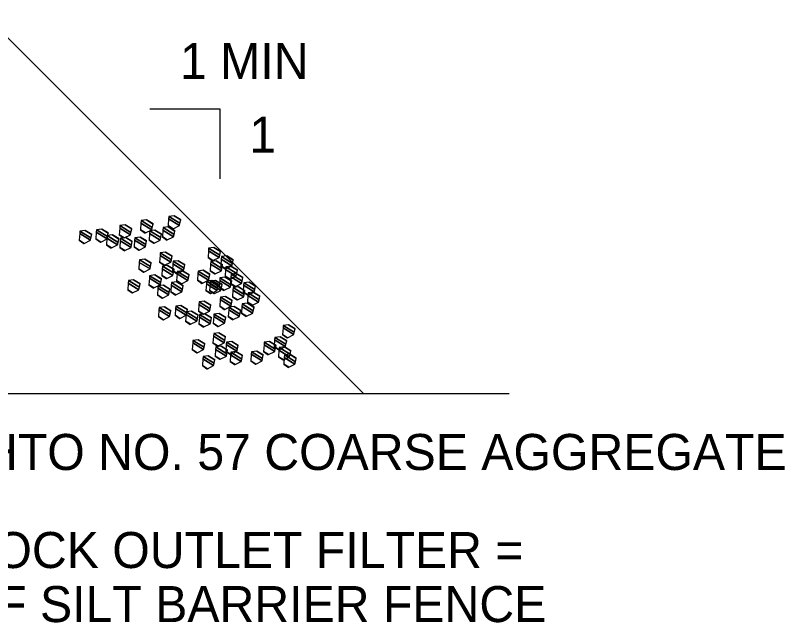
# Model space of a CAD drawing. Extents: x 636462 to 639049, y 299944 to 300538.
# Drawn here: x 637812.7 to 637876.6, y 300272.7 to 300323.2 of the extents above; entities that cross this region are included whole.
import ezdxf

# ---------------------------------------------------------------- set-up
doc = ezdxf.new("R2010")
doc.units = 0
doc.layers.add('Default', color=7, linetype='Continuous')

msp = doc.modelspace()

# ---------------------------------------------------------------- linework, layer by layer
at = {"layer": 'Default'}
for p, q in [((637841.599, 300291.751), (637810.14, 300323.205)), ((637685.207, 300291.751), (637853.724, 300291.751))]:
    msp.add_line(p, q, dxfattribs=at)
msp.add_lwpolyline([(637823.824, 300315.439), (637829.661, 300315.439), (637829.661, 300309.602)], dxfattribs=at)
for points in [[(637823.101, 300305.916), (637823.996, 300305.361), (637824.038, 300305.558), (637823.116, 300306.129)], [(637823.116, 300306.129), (637824.038, 300305.558), (637824.101, 300305.848), (637823.555, 300306.186)], [(637823.555, 300306.186), (637824.101, 300305.848), (637824.103, 300305.858), (637824.103, 300305.858)], [(637825.365, 300305.713), (637825.779, 300305.456), (637826.295, 300305.713), (637825.401, 300306.267)], [(637825.401, 300306.267), (637826.295, 300305.713), (637826.339, 300305.909), (637825.415, 300306.481)], [(637825.415, 300306.481), (637826.339, 300305.909), (637826.403, 300306.196), (637825.852, 300306.538)], [(637825.852, 300306.538), (637826.403, 300306.196), (637826.406, 300306.21), (637826.406, 300306.21)], [(637821.292, 300304.962), (637821.71, 300304.703), (637822.224, 300304.962), (637821.33, 300305.517)], [(637821.33, 300305.517), (637822.224, 300304.962), (637822.267, 300305.157), (637821.344, 300305.729)], [(637821.344, 300305.729), (637822.267, 300305.157), (637822.331, 300305.447), (637821.785, 300305.785)], [(637821.785, 300305.785), (637822.331, 300305.447), (637822.333, 300305.458), (637822.333, 300305.458)], [(637823.061, 300305.361), (637823.476, 300305.104), (637823.996, 300305.361), (637823.101, 300305.916)], [(637824.916, 300305.332), (637825.804, 300304.782), (637825.85, 300304.984), (637824.932, 300305.553)], [(637824.932, 300305.553), (637825.85, 300304.984), (637825.916, 300305.267), (637825.367, 300305.607)], [(637825.745, 300305.44), (637825.745, 300305.44), (637825.779, 300305.456), (637825.365, 300305.713)], [(637825.367, 300305.607), (637825.916, 300305.267), (637825.919, 300305.28), (637825.919, 300305.28)], [(637817.965, 300304.497), (637818.382, 300304.239), (637818.895, 300304.497), (637818.005, 300305.049)], [(637818.005, 300305.049), (637818.895, 300304.497), (637818.939, 300304.694), (637818.021, 300305.264)], [(637818.021, 300305.264), (637818.939, 300304.694), (637819.004, 300304.98), (637818.458, 300305.318)], [(637818.458, 300305.318), (637819.004, 300304.98), (637819.006, 300304.991), (637819.006, 300304.991)], [(637819.344, 300304.608), (637819.76, 300304.35), (637820.278, 300304.608), (637819.382, 300305.164)], [(637819.382, 300305.164), (637820.278, 300304.608), (637820.321, 300304.804), (637819.397, 300305.377)], [(637819.397, 300305.377), (637820.321, 300304.804), (637820.384, 300305.096), (637819.839, 300305.434)], [(637819.839, 300305.434), (637820.384, 300305.096), (637820.386, 300305.104), (637820.386, 300305.104)], [(637820.273, 300304.674), (637821.158, 300304.125), (637821.204, 300304.32), (637820.288, 300304.887)], [(637820.288, 300304.887), (637821.204, 300304.32), (637821.27, 300304.602), (637820.721, 300304.942)], [(637820.721, 300304.942), (637821.27, 300304.602), (637821.273, 300304.614), (637821.273, 300304.614)], [(637821.678, 300304.687), (637821.678, 300304.687), (637821.71, 300304.703), (637821.292, 300304.962)], [(637823.444, 300305.088), (637823.444, 300305.088), (637823.476, 300305.104), (637823.061, 300305.361)], [(637823.771, 300304.517), (637824.185, 300304.261), (637824.7, 300304.517), (637823.81, 300305.069)], [(637823.81, 300305.069), (637824.7, 300304.517), (637824.744, 300304.718), (637823.826, 300305.288)], [(637823.826, 300305.288), (637824.744, 300304.718), (637824.808, 300305.004), (637824.263, 300305.343)], [(637824.263, 300305.343), (637824.808, 300305.004), (637824.811, 300305.015), (637824.811, 300305.015)], [(637824.877, 300304.782), (637825.29, 300304.526), (637825.804, 300304.782), (637824.916, 300305.332)], [(637818.349, 300304.222), (637818.349, 300304.222), (637818.382, 300304.239), (637817.965, 300304.497)], [(637819.73, 300304.335), (637819.73, 300304.335), (637819.76, 300304.35), (637819.344, 300304.608)], [(637820.232, 300304.125), (637820.652, 300303.864), (637821.158, 300304.125), (637820.273, 300304.674)], [(637821.336, 300303.903), (637821.752, 300303.645), (637822.27, 300303.903), (637821.377, 300304.457)], [(637821.377, 300304.457), (637822.27, 300303.903), (637822.313, 300304.1), (637821.393, 300304.671)], [(637821.393, 300304.671), (637822.313, 300304.1), (637822.375, 300304.386), (637821.834, 300304.722)], [(637821.834, 300304.722), (637822.375, 300304.386), (637822.378, 300304.396), (637822.378, 300304.396)], [(637822.529, 300303.947), (637822.946, 300303.688), (637823.462, 300303.947), (637822.57, 300304.5)], [(637822.57, 300304.5), (637823.462, 300303.947), (637823.505, 300304.142), (637822.586, 300304.712)], [(637822.586, 300304.712), (637823.505, 300304.142), (637823.569, 300304.431), (637823.025, 300304.768)], [(637823.025, 300304.768), (637823.569, 300304.431), (637823.571, 300304.44), (637823.571, 300304.44)], [(637824.155, 300304.246), (637824.155, 300304.246), (637824.185, 300304.261), (637823.771, 300304.517)], [(637825.26, 300304.511), (637825.26, 300304.511), (637825.29, 300304.526), (637824.877, 300304.782)], [(637820.616, 300303.846), (637820.616, 300303.846), (637820.652, 300303.864), (637820.232, 300304.125)], [(637821.72, 300303.629), (637821.72, 300303.629), (637821.752, 300303.645), (637821.336, 300303.903)], [(637822.914, 300303.672), (637822.914, 300303.672), (637822.946, 300303.688), (637822.529, 300303.947)], [(637828.674, 300303.071), (637829.088, 300302.814), (637829.608, 300303.071), (637828.713, 300303.626)], [(637828.713, 300303.626), (637829.608, 300303.071), (637829.65, 300303.267), (637828.728, 300303.838)], [(637828.728, 300303.838), (637829.65, 300303.267), (637829.711, 300303.557), (637829.167, 300303.894)], [(637829.167, 300303.894), (637829.711, 300303.557), (637829.713, 300303.567), (637829.713, 300303.567)], [(637822.976, 300302.877), (637823.894, 300302.308), (637823.959, 300302.595), (637823.413, 300302.934)], [(637823.413, 300302.934), (637823.959, 300302.595), (637823.961, 300302.606), (637823.961, 300302.606)], [(637824.647, 300302.685), (637825.059, 300302.43), (637825.581, 300302.685), (637824.685, 300303.241)], [(637824.685, 300303.241), (637825.581, 300302.685), (637825.624, 300302.882), (637824.7, 300303.456)], [(637824.7, 300303.456), (637825.624, 300302.882), (637825.687, 300303.173), (637825.142, 300303.51)], [(637825.142, 300303.51), (637825.687, 300303.173), (637825.688, 300303.18), (637825.688, 300303.18)], [(637829.056, 300302.798), (637829.056, 300302.798), (637829.088, 300302.814), (637828.674, 300303.071)], [(637829.738, 300302.365), (637830.151, 300302.109), (637830.666, 300302.365), (637829.775, 300302.918)], [(637829.775, 300302.918), (637830.666, 300302.365), (637830.711, 300302.563), (637829.79, 300303.134)], [(637829.79, 300303.134), (637830.711, 300302.563), (637830.777, 300302.85), (637830.227, 300303.191)], [(637830.227, 300303.191), (637830.777, 300302.85), (637830.779, 300302.861), (637830.779, 300302.861)], [(637822.922, 300302.111), (637823.339, 300301.852), (637823.85, 300302.111), (637822.961, 300302.662)], [(637822.961, 300302.662), (637823.85, 300302.111), (637823.894, 300302.308), (637822.976, 300302.877)], [(637825.027, 300302.414), (637825.027, 300302.414), (637825.059, 300302.43), (637824.647, 300302.685)], [(637824.862, 300302.134), (637825.757, 300301.579), (637825.8, 300301.777), (637824.877, 300302.349)], [(637824.877, 300302.349), (637825.8, 300301.777), (637825.862, 300302.065), (637825.316, 300302.404)], [(637825.316, 300302.404), (637825.862, 300302.065), (637825.864, 300302.076), (637825.864, 300302.076)], [(637825.709, 300301.979), (637826.122, 300301.723), (637826.639, 300301.979), (637825.749, 300302.531)], [(637825.749, 300302.531), (637826.639, 300301.979), (637826.684, 300302.18), (637825.765, 300302.75)], [(637825.765, 300302.75), (637826.684, 300302.18), (637826.747, 300302.461), (637826.2, 300302.8)], [(637826.2, 300302.8), (637826.747, 300302.461), (637826.75, 300302.475), (637826.75, 300302.475)], [(637828.848, 300301.967), (637829.264, 300301.709), (637829.786, 300301.967), (637828.889, 300302.523)], [(637828.889, 300302.523), (637829.786, 300301.967), (637829.827, 300302.162), (637828.904, 300302.734)], [(637828.904, 300302.734), (637829.827, 300302.162), (637829.888, 300302.454), (637829.345, 300302.79)], [(637829.345, 300302.79), (637829.888, 300302.454), (637829.889, 300302.46), (637829.889, 300302.46)], [(637830.122, 300302.094), (637830.122, 300302.094), (637830.151, 300302.109), (637829.738, 300302.365)], [(637830.13, 300302.076), (637831.02, 300301.524), (637831.064, 300301.723), (637830.146, 300302.293)], [(637830.146, 300302.293), (637831.064, 300301.723), (637831.129, 300302.011), (637830.583, 300302.349)], [(637830.583, 300302.349), (637831.129, 300302.011), (637831.131, 300302.022), (637831.131, 300302.022)], [(637823.306, 300301.836), (637823.306, 300301.836), (637823.339, 300301.852), (637822.922, 300302.111)], [(637824.823, 300301.579), (637825.237, 300301.322), (637825.757, 300301.579), (637824.862, 300302.134)], [(637826.093, 300301.708), (637826.093, 300301.708), (637826.122, 300301.723), (637825.709, 300301.979)], [(637826.061, 300301.14), (637826.474, 300300.883), (637826.995, 300301.14), (637826.101, 300301.694)], [(637826.101, 300301.694), (637826.995, 300301.14), (637827.038, 300301.337), (637826.117, 300301.908)], [(637826.117, 300301.908), (637827.038, 300301.337), (637827.102, 300301.626), (637826.558, 300301.963)], [(637826.558, 300301.963), (637827.102, 300301.626), (637827.102, 300301.629), (637827.102, 300301.629)], [(637827.792, 300301.172), (637828.205, 300300.916), (637828.722, 300301.172), (637827.83, 300301.725)], [(637827.83, 300301.725), (637828.722, 300301.172), (637828.766, 300301.369), (637827.844, 300301.941)], [(637827.844, 300301.941), (637828.766, 300301.369), (637828.83, 300301.656), (637828.279, 300301.997)], [(637828.279, 300301.997), (637828.83, 300301.656), (637828.833, 300301.67), (637828.833, 300301.67)], [(637829.234, 300301.694), (637829.234, 300301.694), (637829.264, 300301.709), (637828.848, 300301.967)], [(637830.089, 300301.524), (637830.505, 300301.267), (637831.02, 300301.524), (637830.13, 300302.076)], [(637830.571, 300301.461), (637831.465, 300300.907), (637831.507, 300301.105), (637830.587, 300301.676)], [(637830.587, 300301.676), (637831.507, 300301.105), (637831.569, 300301.397), (637831.028, 300301.732)], [(637831.028, 300301.732), (637831.569, 300301.397), (637831.57, 300301.403), (637831.57, 300301.403)], [(637822.034, 300300.938), (637822.922, 300300.387), (637822.967, 300300.585), (637822.05, 300301.154)], [(637822.05, 300301.154), (637822.967, 300300.585), (637823.033, 300300.873), (637822.485, 300301.213)], [(637822.485, 300301.213), (637823.033, 300300.873), (637823.035, 300300.883), (637823.035, 300300.883)], [(637823.763, 300300.788), (637824.18, 300300.529), (637824.693, 300300.788), (637823.804, 300301.339)], [(637823.804, 300301.339), (637824.693, 300300.788), (637824.737, 300300.981), (637823.82, 300301.55)], [(637823.82, 300301.55), (637824.737, 300300.981), (637824.803, 300301.272), (637824.257, 300301.611)], [(637824.257, 300301.611), (637824.803, 300301.272), (637824.805, 300301.277), (637824.805, 300301.277)], [(637825.207, 300301.308), (637825.207, 300301.308), (637825.237, 300301.322), (637824.823, 300301.579)], [(637825.63, 300300.98), (637826.552, 300300.408), (637826.615, 300300.696), (637826.069, 300301.035)], [(637826.445, 300300.869), (637826.445, 300300.869), (637826.474, 300300.883), (637826.061, 300301.14)], [(637826.069, 300301.035), (637826.615, 300300.696), (637826.617, 300300.707), (637826.617, 300300.707)], [(637828.17, 300300.899), (637828.17, 300300.899), (637828.205, 300300.916), (637827.792, 300301.172)], [(637828.537, 300300.885), (637829.43, 300300.331), (637829.473, 300300.529), (637828.552, 300301.099)], [(637828.552, 300301.099), (637829.473, 300300.529), (637829.535, 300300.818), (637828.993, 300301.154)], [(637828.846, 300300.884), (637829.738, 300300.331), (637829.782, 300300.527), (637828.86, 300301.099)], [(637828.86, 300301.099), (637829.782, 300300.527), (637829.848, 300300.812), (637829.297, 300301.154)], [(637828.993, 300301.154), (637829.535, 300300.818), (637829.537, 300300.826), (637829.537, 300300.826)], [(637829.297, 300301.154), (637829.848, 300300.812), (637829.851, 300300.826), (637829.851, 300300.826)], [(637829.602, 300300.602), (637830.023, 300300.341), (637830.536, 300300.602), (637829.643, 300301.156)], [(637829.643, 300301.156), (637830.536, 300300.602), (637830.578, 300300.792), (637829.659, 300301.362)], [(637829.659, 300301.362), (637830.578, 300300.792), (637830.641, 300301.082), (637830.098, 300301.419)], [(637830.474, 300301.251), (637830.474, 300301.251), (637830.505, 300301.267), (637830.089, 300301.524)], [(637830.098, 300301.419), (637830.641, 300301.082), (637830.644, 300301.091), (637830.644, 300301.091)], [(637830.53, 300300.907), (637830.946, 300300.65), (637831.465, 300300.907), (637830.571, 300301.461)], [(637831.647, 300300.97), (637832.569, 300300.398), (637832.633, 300300.679), (637832.086, 300301.018)], [(637832.086, 300301.018), (637832.633, 300300.679), (637832.636, 300300.691), (637832.636, 300300.691)], [(637821.993, 300300.387), (637822.407, 300300.131), (637822.922, 300300.387), (637822.034, 300300.938)], [(637822.378, 300300.116), (637822.378, 300300.116), (637822.407, 300300.131), (637821.993, 300300.387)], [(637824.147, 300300.513), (637824.147, 300300.513), (637824.18, 300300.529), (637823.763, 300300.788)], [(637824.467, 300299.947), (637824.883, 300299.688), (637825.403, 300299.947), (637824.508, 300300.502)], [(637824.508, 300300.502), (637825.403, 300299.947), (637825.445, 300300.144), (637824.524, 300300.715)], [(637824.524, 300300.715), (637825.445, 300300.144), (637825.506, 300300.43), (637824.964, 300300.766)], [(637824.964, 300300.766), (637825.506, 300300.43), (637825.508, 300300.44), (637825.508, 300300.44)], [(637825.573, 300300.209), (637825.987, 300299.953), (637826.51, 300300.209), (637825.614, 300300.765)], [(637825.614, 300300.765), (637826.51, 300300.209), (637826.552, 300300.408), (637825.63, 300300.98)], [(637828.496, 300300.331), (637828.912, 300300.073), (637829.43, 300300.331), (637828.537, 300300.885)], [(637828.809, 300300.331), (637829.224, 300300.074), (637829.738, 300300.331), (637828.846, 300300.884)], [(637829.986, 300300.323), (637829.986, 300300.323), (637830.023, 300300.341), (637829.602, 300300.602)], [(637830.915, 300300.634), (637830.915, 300300.634), (637830.946, 300300.65), (637830.53, 300300.907)], [(637830.706, 300299.803), (637831.122, 300299.545), (637831.643, 300299.803), (637830.747, 300300.358)], [(637830.747, 300300.358), (637831.643, 300299.803), (637831.685, 300300), (637830.763, 300300.571)], [(637830.763, 300300.571), (637831.685, 300300), (637831.747, 300300.291), (637831.204, 300300.628)], [(637831.204, 300300.628), (637831.747, 300300.291), (637831.748, 300300.294), (637831.748, 300300.294)], [(637831.594, 300300.203), (637832.014, 300299.943), (637832.524, 300300.203), (637831.632, 300300.757)], [(637831.632, 300300.757), (637832.524, 300300.203), (637832.569, 300300.398), (637831.647, 300300.97)], [(637824.853, 300299.673), (637824.853, 300299.673), (637824.883, 300299.688), (637824.467, 300299.947)], [(637825.957, 300299.938), (637825.957, 300299.938), (637825.987, 300299.953), (637825.573, 300300.209)], [(637828.882, 300300.058), (637828.882, 300300.058), (637828.912, 300300.073), (637828.496, 300300.331)], [(637829.191, 300300.058), (637829.191, 300300.058), (637829.224, 300300.074), (637828.809, 300300.331)], [(637829.687, 300299.561), (637830.579, 300299.008), (637830.623, 300299.201), (637829.701, 300299.773)], [(637829.701, 300299.773), (637830.623, 300299.201), (637830.688, 300299.486), (637830.138, 300299.827)], [(637830.138, 300299.827), (637830.688, 300299.486), (637830.69, 300299.498), (637830.69, 300299.498)], [(637831.091, 300299.53), (637831.091, 300299.53), (637831.122, 300299.545), (637830.706, 300299.803)], [(637831.98, 300299.926), (637831.98, 300299.926), (637832.014, 300299.943), (637831.594, 300300.203)], [(637831.946, 300299.36), (637832.361, 300299.103), (637832.876, 300299.36), (637831.988, 300299.911)], [(637831.988, 300299.911), (637832.876, 300299.36), (637832.921, 300299.556), (637832.005, 300300.125)], [(637832.005, 300300.125), (637832.921, 300299.556), (637832.988, 300299.845), (637832.442, 300300.183)], [(637832.442, 300300.183), (637832.988, 300299.845), (637832.99, 300299.853), (637832.99, 300299.853)], [(637825.986, 300299.018), (637826.906, 300298.448), (637826.973, 300298.738), (637826.423, 300299.079)], [(637826.423, 300299.079), (637826.973, 300298.738), (637826.975, 300298.747), (637826.975, 300298.747)], [(637827.879, 300298.608), (637828.292, 300298.351), (637828.809, 300298.608), (637827.915, 300299.162)], [(637827.915, 300299.162), (637828.809, 300298.608), (637828.854, 300298.805), (637827.929, 300299.378)], [(637827.929, 300299.378), (637828.854, 300298.805), (637828.918, 300299.089), (637828.366, 300299.431)], [(637828.366, 300299.431), (637828.918, 300299.089), (637828.92, 300299.101), (637828.92, 300299.101)], [(637829.649, 300299.008), (637830.064, 300298.751), (637830.579, 300299.008), (637829.687, 300299.561)], [(637831.499, 300298.986), (637832.393, 300298.432), (637832.436, 300298.629), (637831.515, 300299.2)], [(637831.515, 300299.2), (637832.436, 300298.629), (637832.499, 300298.918), (637831.956, 300299.255)], [(637832.332, 300299.089), (637832.332, 300299.089), (637832.361, 300299.103), (637831.946, 300299.36)], [(637831.956, 300299.255), (637832.499, 300298.918), (637832.5, 300298.923), (637832.5, 300298.923)], [(637824.548, 300298.144), (637824.968, 300297.884), (637825.478, 300298.144), (637824.587, 300298.697)], [(637824.587, 300298.697), (637825.478, 300298.144), (637825.521, 300298.337), (637824.602, 300298.907)], [(637824.602, 300298.907), (637825.521, 300298.337), (637825.586, 300298.625), (637825.045, 300298.96)], [(637825.045, 300298.96), (637825.586, 300298.625), (637825.587, 300298.632), (637825.587, 300298.632)], [(637825.933, 300298.256), (637826.344, 300298.001), (637826.862, 300298.256), (637825.971, 300298.808)], [(637825.971, 300298.808), (637826.862, 300298.256), (637826.906, 300298.448), (637825.986, 300299.018)], [(637826.854, 300298.322), (637827.747, 300297.768), (637827.79, 300297.964), (637826.87, 300298.535)], [(637826.87, 300298.535), (637827.79, 300297.964), (637827.853, 300298.255), (637827.311, 300298.591)], [(637827.311, 300298.591), (637827.853, 300298.255), (637827.855, 300298.264), (637827.855, 300298.264)], [(637828.263, 300298.337), (637828.263, 300298.337), (637828.292, 300298.351), (637827.879, 300298.608)], [(637830.029, 300298.733), (637830.029, 300298.733), (637830.064, 300298.751), (637829.649, 300299.008)], [(637830.354, 300298.169), (637830.773, 300297.909), (637831.289, 300298.169), (637830.395, 300298.723)], [(637830.395, 300298.723), (637831.289, 300298.169), (637831.331, 300298.363), (637830.411, 300298.933)], [(637830.411, 300298.933), (637831.331, 300298.363), (637831.395, 300298.65), (637830.85, 300298.988)], [(637830.85, 300298.988), (637831.395, 300298.65), (637831.396, 300298.656), (637831.396, 300298.656)], [(637831.459, 300298.432), (637831.875, 300298.174), (637832.393, 300298.432), (637831.499, 300298.986)], [(637831.845, 300298.159), (637831.845, 300298.159), (637831.875, 300298.174), (637831.459, 300298.432)], [(637824.932, 300297.865), (637824.932, 300297.865), (637824.968, 300297.884), (637824.548, 300298.144)], [(637826.311, 300297.985), (637826.311, 300297.985), (637826.344, 300298.001), (637825.933, 300298.256)], [(637826.813, 300297.768), (637827.229, 300297.51), (637827.747, 300297.768), (637826.854, 300298.322)], [(637827.921, 300297.546), (637828.338, 300297.288), (637828.858, 300297.546), (637827.961, 300298.102)], [(637827.961, 300298.102), (637828.858, 300297.546), (637828.898, 300297.741), (637827.976, 300298.312)], [(637827.976, 300298.312), (637828.898, 300297.741), (637828.959, 300298.032), (637828.415, 300298.369)], [(637828.415, 300298.369), (637828.959, 300298.032), (637828.961, 300298.041), (637828.961, 300298.041)], [(637829.115, 300297.592), (637829.53, 300297.335), (637830.049, 300297.592), (637829.153, 300298.148)], [(637829.153, 300298.148), (637830.049, 300297.592), (637830.091, 300297.788), (637829.167, 300298.361)], [(637829.167, 300298.361), (637830.091, 300297.788), (637830.155, 300298.08), (637829.61, 300298.418)], [(637829.61, 300298.418), (637830.155, 300298.08), (637830.156, 300298.086), (637830.156, 300298.086)], [(637830.739, 300297.892), (637830.739, 300297.892), (637830.773, 300297.909), (637830.354, 300298.169)], [(637827.199, 300297.495), (637827.199, 300297.495), (637827.229, 300297.51), (637826.813, 300297.768)], [(637828.304, 300297.271), (637828.304, 300297.271), (637828.338, 300297.288), (637827.921, 300297.546)], [(637829.499, 300297.319), (637829.499, 300297.319), (637829.53, 300297.335), (637829.115, 300297.592)], [(637834.871, 300296.654), (637835.288, 300296.395), (637835.809, 300296.654), (637834.912, 300297.21)], [(637834.912, 300297.21), (637835.809, 300296.654), (637835.849, 300296.845), (637834.927, 300297.416)], [(637834.927, 300297.416), (637835.849, 300296.845), (637835.91, 300297.135), (637835.368, 300297.471)], [(637835.368, 300297.471), (637835.91, 300297.135), (637835.912, 300297.143), (637835.912, 300297.143)], [(637829.088, 300295.972), (637829.505, 300295.714), (637830.023, 300295.972), (637829.131, 300296.525)], [(637829.131, 300296.525), (637830.023, 300295.972), (637830.066, 300296.169), (637829.147, 300296.739)], [(637829.147, 300296.739), (637830.066, 300296.169), (637830.128, 300296.457), (637829.586, 300296.793)], [(637829.586, 300296.793), (637830.128, 300296.457), (637830.13, 300296.464), (637830.13, 300296.464)], [(637835.255, 300296.379), (637835.255, 300296.379), (637835.288, 300296.395), (637834.871, 300296.654)], [(637827.367, 300295.398), (637827.782, 300295.14), (637828.298, 300295.398), (637827.404, 300295.952)], [(637827.404, 300295.952), (637828.298, 300295.398), (637828.342, 300295.594), (637827.418, 300296.167)], [(637827.418, 300296.167), (637828.342, 300295.594), (637828.407, 300295.881), (637827.855, 300296.223)], [(637827.855, 300296.223), (637828.407, 300295.881), (637828.409, 300295.889), (637828.409, 300295.889)], [(637829.475, 300295.699), (637829.475, 300295.699), (637829.505, 300295.714), (637829.088, 300295.972)], [(637830.191, 300295.819), (637831.082, 300295.266), (637831.126, 300295.458), (637830.205, 300296.029)], [(637830.205, 300296.029), (637831.126, 300295.458), (637831.192, 300295.748), (637830.644, 300296.088)], [(637830.644, 300296.088), (637831.192, 300295.748), (637831.194, 300295.756), (637831.194, 300295.756)], [(637833.334, 300295.805), (637834.225, 300295.252), (637834.269, 300295.451), (637833.35, 300296.021)], [(637833.35, 300296.021), (637834.269, 300295.451), (637834.333, 300295.741), (637833.791, 300296.078)], [(637833.791, 300296.078), (637834.333, 300295.741), (637834.335, 300295.75), (637834.335, 300295.75)], [(637834.177, 300295.653), (637834.594, 300295.394), (637835.111, 300295.653), (637834.216, 300296.208)], [(637834.216, 300296.208), (637835.111, 300295.653), (637835.154, 300295.847), (637834.231, 300296.419)], [(637834.231, 300296.419), (637835.154, 300295.847), (637835.216, 300296.133), (637834.67, 300296.472)], [(637834.67, 300296.472), (637835.216, 300296.133), (637835.218, 300296.142), (637835.218, 300296.142)], [(637827.751, 300295.125), (637827.751, 300295.125), (637827.782, 300295.14), (637827.367, 300295.398)], [(637829.264, 300294.868), (637829.68, 300294.61), (637830.199, 300294.868), (637829.305, 300295.422)], [(637829.305, 300295.422), (637830.199, 300294.868), (637830.242, 300295.064), (637829.321, 300295.635)], [(637829.321, 300295.635), (637830.242, 300295.064), (637830.305, 300295.352), (637829.762, 300295.689)], [(637829.762, 300295.689), (637830.305, 300295.352), (637830.306, 300295.355), (637830.306, 300295.355)], [(637830.154, 300295.266), (637830.573, 300295.007), (637831.082, 300295.266), (637830.191, 300295.819)], [(637830.538, 300294.989), (637830.538, 300294.989), (637830.573, 300295.007), (637830.154, 300295.266)], [(637830.563, 300295.19), (637831.481, 300294.62), (637831.547, 300294.905), (637831, 300295.244)], [(637831, 300295.244), (637831.547, 300294.905), (637831.55, 300294.917), (637831.55, 300294.917)], [(637832.284, 300295.222), (637833.208, 300294.649), (637833.272, 300294.938), (637832.727, 300295.277)], [(637832.727, 300295.277), (637833.272, 300294.938), (637833.275, 300294.949), (637833.275, 300294.949)], [(637833.293, 300295.252), (637833.708, 300294.995), (637834.225, 300295.252), (637833.334, 300295.805)], [(637833.677, 300294.979), (637833.677, 300294.979), (637833.708, 300294.995), (637833.293, 300295.252)], [(637834.561, 300295.378), (637834.561, 300295.378), (637834.594, 300295.394), (637834.177, 300295.653)], [(637834.535, 300294.813), (637834.95, 300294.556), (637835.463, 300294.813), (637834.573, 300295.366)], [(637834.573, 300295.366), (637835.463, 300294.813), (637835.508, 300295.011), (637834.587, 300295.582)], [(637834.587, 300295.582), (637835.508, 300295.011), (637835.573, 300295.295), (637835.024, 300295.635)], [(637835.024, 300295.635), (637835.573, 300295.295), (637835.574, 300295.303), (637835.574, 300295.303)], [(637828.206, 300294.069), (637828.621, 300293.812), (637829.137, 300294.069), (637828.246, 300294.622)], [(637828.246, 300294.622), (637829.137, 300294.069), (637829.181, 300294.267), (637828.261, 300294.838)], [(637828.261, 300294.838), (637829.181, 300294.267), (637829.245, 300294.553), (637828.698, 300294.892)], [(637828.698, 300294.892), (637829.245, 300294.553), (637829.248, 300294.565), (637829.248, 300294.565)], [(637829.649, 300294.595), (637829.649, 300294.595), (637829.68, 300294.61), (637829.264, 300294.868)], [(637830.506, 300294.421), (637830.92, 300294.165), (637831.434, 300294.421), (637830.547, 300294.972)], [(637830.547, 300294.972), (637831.434, 300294.421), (637831.481, 300294.62), (637830.563, 300295.19)], [(637832.233, 300294.462), (637832.655, 300294.2), (637833.166, 300294.462), (637832.27, 300295.017)], [(637832.27, 300295.017), (637833.166, 300294.462), (637833.208, 300294.649), (637832.284, 300295.222)], [(637834.919, 300294.54), (637834.919, 300294.54), (637834.95, 300294.556), (637834.535, 300294.813)], [(637834.976, 300294.197), (637835.393, 300293.938), (637835.906, 300294.197), (637835.017, 300294.748)], [(637835.017, 300294.748), (637835.906, 300294.197), (637835.951, 300294.392), (637835.032, 300294.961)], [(637835.032, 300294.961), (637835.951, 300294.392), (637836.015, 300294.673), (637835.469, 300295.012)], [(637835.469, 300295.012), (637836.015, 300294.673), (637836.017, 300294.684), (637836.017, 300294.684)], [(637828.589, 300293.796), (637828.589, 300293.796), (637828.621, 300293.812), (637828.206, 300294.069)], [(637830.89, 300294.15), (637830.89, 300294.15), (637830.92, 300294.165), (637830.506, 300294.421)], [(637832.62, 300294.182), (637832.62, 300294.182), (637832.655, 300294.2), (637832.233, 300294.462)], [(637835.36, 300293.922), (637835.36, 300293.922), (637835.393, 300293.938), (637834.976, 300294.197)]]:
    msp.add_lwpolyline(points, close=True, dxfattribs=at)

# ---------------------------------------------------------------- texts
for s, height, p in [('1 MIN', 2.998, (637826.34, 300317.908)), ('1', 2.998, (637832.108, 300311.784)), ('AASHTO NO. 57 COARSE AGGREGATE', 2.99804, (637801.942, 300285.387)), ('HEIGHT OF ROCK OUTLET FILTER =', 2.99804, (637785.076, 300277.231)), ('5/6 HEIGHT OF SILT BARRIER FENCE', 2.99804, (637785.076, 300272.734))]:
    msp.add_text(s, height=height, dxfattribs=at).set_placement(p)

doc.saveas('drawing.dxf')
